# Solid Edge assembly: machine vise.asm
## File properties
Author: Robert a Rhodes jr
Template: Normal.asm
Last saved by: Cadcim
Revision: 24
Application: Solid Edge
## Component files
slide key.par
base.par
Sliding jaw.par
vise screw.par
collar.par
handle rod.par
handle ball.par
jaw plate.par
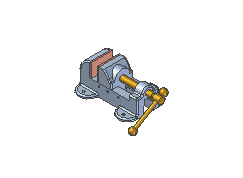
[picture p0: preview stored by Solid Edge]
